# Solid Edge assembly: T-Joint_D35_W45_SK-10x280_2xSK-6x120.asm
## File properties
Author: fknapp
Template: iso metric assembly.asm
Last saved by: fknapp
Revision: 10
Application: Solid Edge
Username: fknapp
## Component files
T-Joint_D35_W45.par
SK Schraube 6x120_ohne_Gewinde.par
SK Schraube 10x280_ohne_Gewinde_22042020.par
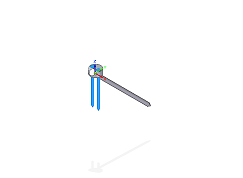
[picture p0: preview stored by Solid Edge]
